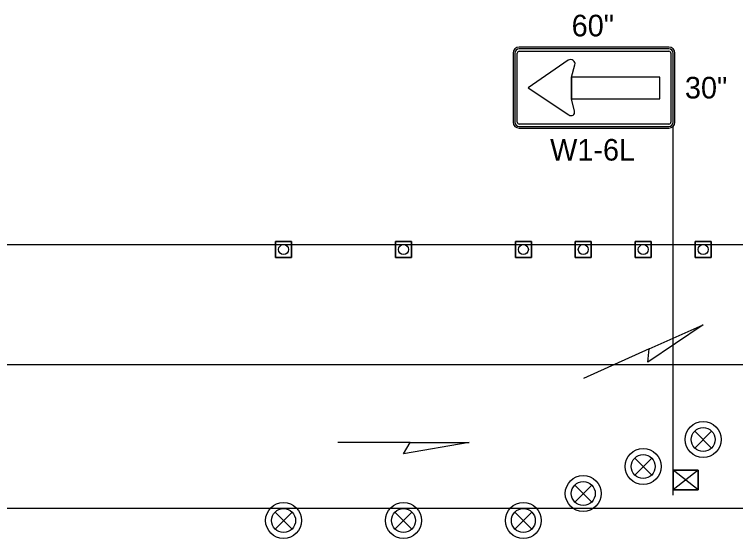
# Model space of a CAD drawing. Extents: x 99999 to 100116, y 99995 to 100013.
# Drawn here: x 100026.677 to 100029.084, y 100006.016 to 100007.763 of the extents above; entities that cross this region are included whole.
import ezdxf

# ---------------------------------------------------------------- set-up
doc = ezdxf.new("R2010")
doc.units = 0
for name, color, linetype in [('RD_ED_ShoulderPavedEdge', 7, 'Continuous'), ('RD_MK_LineEdgeYellow', 7, 'Continuous'), ('RD_MK_LineLane', 7, 'Continuous'), ('TR_SN_ConstructionSigns', 7, 'Continuous'), ('TR_WZ_PortableSignMount5ftMinBlk-Org', 7, 'Continuous'), ('TR_WZ_TrafficCone', 7, 'Continuous'), ('TR_WZ_TrafficSafetyDrum', 7, 'Continuous'), ('TR_WZ_WorkZoneDetails', 7, 'Continuous')]:
    doc.layers.add(name, color=color, linetype=linetype)

msp = doc.modelspace()

# ---------------------------------------------------------------- linework, layer by layer
at = {"layer": 'RD_ED_ShoulderPavedEdge'}
msp.add_line((100021.7753, 100006.9957), (100035.62, 100006.9957), dxfattribs=at)
at = {"layer": 'RD_MK_LineEdgeYellow'}
msp.add_line((100021.7753, 100006.5957), (100035.62, 100006.5957), dxfattribs=at)
at = {"layer": 'RD_MK_LineLane'}
msp.add_lwpolyline([(100035.62, 100006.1157), (100021.7753, 100006.1157)], dxfattribs=at)
at = {"layer": 'TR_SN_ConstructionSigns'}
for p, q in [((100028.861, 100007.6537), (100028.3615, 100007.6537)), ((100028.861, 100007.6481), (100028.3615, 100007.6481)), ((100028.3413, 100007.6335), (100028.3413, 100007.404)), ((100028.3469, 100007.6335), (100028.3469, 100007.404)), ((100028.3548, 100007.404), (100028.3548, 100007.6335)), ((100028.3615, 100007.6402), (100028.861, 100007.6402)), ((100028.8678, 100007.6335), (100028.8678, 100007.404)), ((100028.8756, 100007.404), (100028.8756, 100007.6335)), ((100028.8813, 100007.404), (100028.8813, 100007.6335)), ((100028.5251, 100007.6099), (100028.3919, 100007.518)), ((100028.536, 100007.554), (100028.5476, 100007.5946)), ((100028.536, 100007.5522), (100028.536, 100007.554)), ((100028.8306, 100007.554), (100028.536, 100007.554)), ((100028.536, 100007.554), (100028.536, 100007.5522)), ((100028.536, 100007.4838), (100028.536, 100007.5522)), ((100028.536, 100007.5522), (100028.536, 100007.4838)), ((100028.8306, 100007.482), (100028.8306, 100007.554)), ((100028.3919, 100007.518), (100028.5269, 100007.4278)), ((100028.536, 100007.482), (100028.536, 100007.4838)), ((100028.536, 100007.4838), (100028.536, 100007.482)), ((100028.5455, 100007.4401), (100028.536, 100007.482)), ((100028.536, 100007.482), (100028.8306, 100007.482)), ((100028.861, 100007.3972), (100028.3615, 100007.3972)), ((100028.3615, 100007.3894), (100028.861, 100007.3894)), ((100028.3615, 100007.3837), (100028.861, 100007.3837))]:
    msp.add_line(p, q, dxfattribs=at)
for centre, radius, start, end in [((100028.3615, 100007.6335), 0.0202, 90, 180), ((100028.3615, 100007.6335), 0.0146, 90, 180), ((100028.861, 100007.6335), 0.0202, 360, 90), ((100028.861, 100007.6335), 0.0146, 360, 90), ((100028.3615, 100007.6335), 0.00675, 90, 180), ((100028.861, 100007.6335), 0.00675, 360, 90), ((100028.3615, 100007.404), 0.0202, 180, 270), ((100028.3615, 100007.404), 0.0146, 180, 270), ((100028.3615, 100007.404), 0.00675, 180, 270), ((100028.861, 100007.404), 0.0202, 270, 0), ((100028.861, 100007.404), 0.0146, 270, 0), ((100028.861, 100007.404), 0.00675, 270, 0)]:
    msp.add_arc(centre, radius, start, end, dxfattribs=at)
for centre, major_axis, ratio, start_param, end_param in [((100028.5334, 100007.5985), (0.0142, -0.0039), 0.918316, 0, 2.426314), ((100028.5334, 100007.4376), (0.0109, -0.0073), 0.895682, 4.712389, 7.138703)]:
    msp.add_ellipse(centre, major_axis=major_axis, ratio=ratio, start_param=start_param, end_param=end_param, dxfattribs=at)
at = {"layer": 'TR_WZ_PortableSignMount5ftMinBlk-Org'}
for p, q in [((100028.8753, 100006.1607), (100028.8753, 100006.2607)), ((100028.9587, 100006.2432), (100028.8753, 100006.1782)), ((100028.9587, 100006.1782), (100028.8753, 100006.2432)), ((100028.917, 100006.2107), (100028.917, 100006.2107)), ((100028.9172, 100006.2108), (100028.9172, 100006.2108))]:
    msp.add_line(p, q, dxfattribs=at)
for points in [[(100028.9587, 100006.2432), (100028.9587, 100006.1782), (100028.8753, 100006.1782), (100028.8753, 100006.2432)], [(100028.8753, 100006.1782), (100028.9587, 100006.1782), (100028.9587, 100006.2432), (100028.8753, 100006.2432)]]:
    msp.add_lwpolyline(points, close=True, dxfattribs=at)
at = {"layer": 'TR_WZ_TrafficCone'}
for points in [[(100027.5487, 100006.9524), (100027.602, 100006.9524), (100027.602, 100007.0057), (100027.5487, 100007.0057), (100027.5487, 100006.9524)], [(100027.5487, 100007.0057), (100027.602, 100007.0057), (100027.602, 100006.9524), (100027.5487, 100006.9524), (100027.5487, 100007.0057)], [(100027.9487, 100006.9524), (100028.002, 100006.9524), (100028.002, 100007.0057), (100027.9487, 100007.0057), (100027.9487, 100006.9524)], [(100027.9487, 100007.0057), (100028.002, 100007.0057), (100028.002, 100006.9524), (100027.9487, 100006.9524), (100027.9487, 100007.0057)], [(100028.3487, 100006.9524), (100028.402, 100006.9524), (100028.402, 100007.0057), (100028.3487, 100007.0057), (100028.3487, 100006.9524)], [(100028.3487, 100007.0057), (100028.402, 100007.0057), (100028.402, 100006.9524), (100028.3487, 100006.9524), (100028.3487, 100007.0057)], [(100028.5487, 100006.9524), (100028.602, 100006.9524), (100028.602, 100007.0057), (100028.5487, 100007.0057), (100028.5487, 100006.9524)], [(100028.5487, 100007.0057), (100028.602, 100007.0057), (100028.602, 100006.9524), (100028.5487, 100006.9524), (100028.5487, 100007.0057)], [(100028.7487, 100006.9524), (100028.802, 100006.9524), (100028.802, 100007.0057), (100028.7487, 100007.0057), (100028.7487, 100006.9524)], [(100028.7487, 100007.0057), (100028.802, 100007.0057), (100028.802, 100006.9524), (100028.7487, 100006.9524), (100028.7487, 100007.0057)], [(100028.9487, 100006.9524), (100029.002, 100006.9524), (100029.002, 100007.0057), (100028.9487, 100007.0057), (100028.9487, 100006.9524)], [(100028.9487, 100007.0057), (100029.002, 100007.0057), (100029.002, 100006.9524), (100028.9487, 100006.9524), (100028.9487, 100007.0057)]]:
    msp.add_lwpolyline(points, dxfattribs=at)
for centre in [(100027.5753, 100006.9791), (100027.9753, 100006.9791), (100028.3753, 100006.9791), (100028.5753, 100006.9791), (100028.7753, 100006.9791), (100028.9753, 100006.9791)]:
    msp.add_circle(centre, 0.0167, dxfattribs=at)
at = {"layer": 'TR_WZ_TrafficSafetyDrum'}
for p, q in [((100028.947, 100006.374), (100029.0036, 100006.3174)), ((100029.0036, 100006.374), (100028.947, 100006.3174)), ((100028.747, 100006.284), (100028.8036, 100006.2274)), ((100028.8036, 100006.284), (100028.747, 100006.2274)), ((100028.547, 100006.194), (100028.6036, 100006.1374)), ((100028.6036, 100006.194), (100028.547, 100006.1374)), ((100027.547, 100006.104), (100027.6036, 100006.0474)), ((100027.6036, 100006.104), (100027.547, 100006.0474)), ((100027.947, 100006.104), (100028.0036, 100006.0474)), ((100028.0036, 100006.104), (100027.947, 100006.0474)), ((100028.347, 100006.104), (100028.4036, 100006.0474)), ((100028.4036, 100006.104), (100028.347, 100006.0474))]:
    msp.add_line(p, q, dxfattribs=at)
for centre, radius in [((100028.9753, 100006.3457), 0.06), ((100028.9753, 100006.3457), 0.06), ((100028.9753, 100006.3457), 0.04), ((100028.7753, 100006.2557), 0.06), ((100028.7753, 100006.2557), 0.06), ((100028.7753, 100006.2557), 0.04), ((100028.5753, 100006.1657), 0.06), ((100028.5753, 100006.1657), 0.06), ((100028.5753, 100006.1657), 0.04), ((100027.5753, 100006.0757), 0.06), ((100027.5753, 100006.0757), 0.06), ((100027.9753, 100006.0757), 0.06), ((100027.9753, 100006.0757), 0.06), ((100028.3753, 100006.0757), 0.06), ((100028.3753, 100006.0757), 0.06), ((100027.5753, 100006.0757), 0.04), ((100027.9753, 100006.0757), 0.04), ((100028.3753, 100006.0757), 0.04)]:
    msp.add_circle(centre, radius, dxfattribs=at)
at = {"layer": 'TR_WZ_WorkZoneDetails'}
for p, q in [((100028.8753, 100006.2607), (100028.8753, 100007.3897)), ((100028.7956, 100006.6477), (100028.5757, 100006.5488)), ((100027.9976, 100006.3364), (100027.7565, 100006.3364))]:
    msp.add_line(p, q, dxfattribs=at)
for points in [[(100028.9748, 100006.7283), (100028.7911, 100006.6034), (100028.7956, 100006.6477)], [(100028.1941, 100006.3364), (100027.9753, 100006.2979), (100027.9976, 100006.3364)]]:
    msp.add_lwpolyline(points, close=True, dxfattribs=at)

# ---------------------------------------------------------------- texts
at = {"layer": 'TR_SN_ConstructionSigns'}
for s, p in [('60"', (100028.5365, 100007.6897)), ('30"', (100028.9145, 100007.4827)), ('W1-6L', (100028.4646, 100007.2757))]:
    msp.add_text(s, height=0.072, rotation=360, dxfattribs=at).set_placement(p)

doc.saveas('drawing.dxf')
